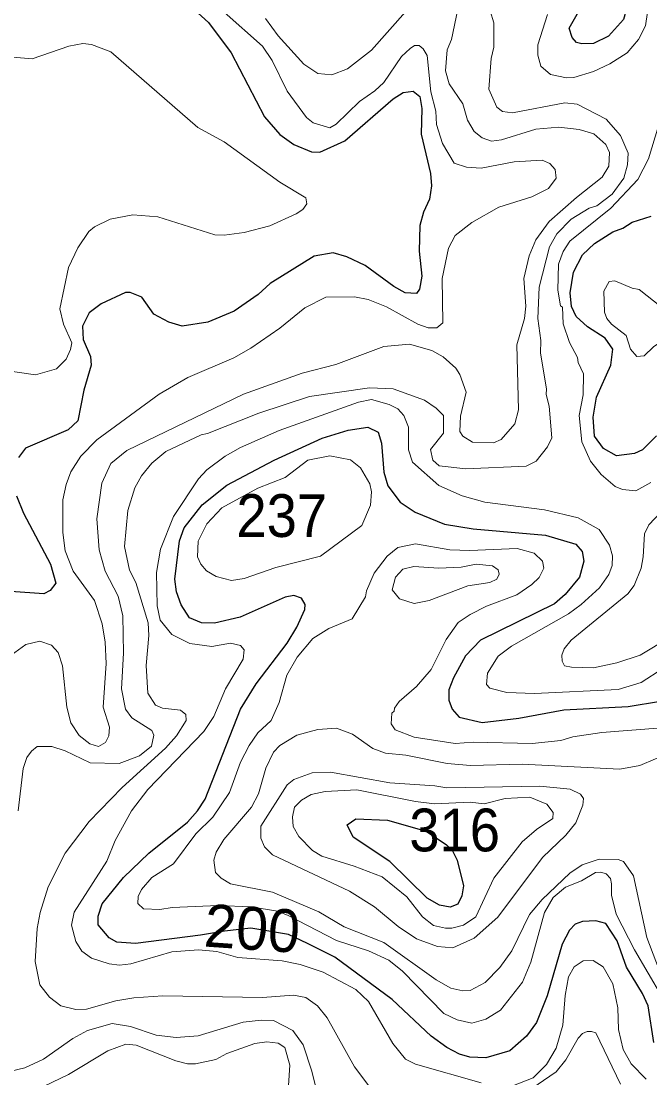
# Model space of a CAD drawing. Extents: x 673.6 to 698.9, y 7012 to 7040.1.
# Drawn here: x 676.978 to 678.153, y 7028.029 to 7030.005 of the extents above; entities that cross this region are included whole.
import ezdxf
from ezdxf.enums import TextEntityAlignment as Align

# ---------------------------------------------------------------- set-up
doc = ezdxf.new("R2010")
doc.units = 0
doc.header["$LTSCALE"] = 0.032
doc.layers.add('1', color=7, linetype='Continuous', lineweight=25)
doc.layers.add('2', color=7, linetype='Continuous', lineweight=13)
doc.layers.add('21', color=7, linetype='Continuous')
doc.layers.add('61', color=7, linetype='Continuous')

msp = doc.modelspace()

# ---------------------------------------------------------------- linework, layer by layer
at = {"layer": '1'}
for points in [[(678.0411, 7030.152), (678.055, 7030.1506), (678.0674, 7030.144), (678.0753, 7030.1312), (678.1044, 7030.0835), (678.1131, 7030.0614), (678.1126, 7030.0395), (678.1039, 7030.0088), (678.0755, 7029.9773), (678.0473, 7029.9638), (678.0256, 7029.9627), (678.016, 7029.9657), (678.0077, 7029.9748), (678.002, 7029.9921), (678.0193, 7030.0227), (678.0451, 7030.0581), (678.0459, 7030.0806), (678.024, 7030.1306), (678.0252, 7030.1378), (678.0316, 7030.1469)], [(677.7731, 7028.4653), (677.7832, 7028.4554), (677.7926, 7028.4367), (677.8046, 7028.3884), (677.8016, 7028.3696), (677.7941, 7028.3539), (677.7799, 7028.3486), (677.7597, 7028.3521), (677.7368, 7028.3655), (677.6671, 7028.4341), (677.5986, 7028.4792), (677.5871, 7028.5023), (677.6031, 7028.514), (677.6623, 7028.5114), (677.7346, 7028.4909)]]:
    msp.add_lwpolyline(points, close=True, dxfattribs=at)
for points in [[(677.2764, 7030.0503), (677.3282, 7030.0026), (677.3702, 7029.9463), (677.4325, 7029.8263), (677.4613, 7029.7932), (677.4875, 7029.7745), (677.5207, 7029.7609), (677.5362, 7029.7607), (677.5826, 7029.7816), (677.6731, 7029.8602), (677.6916, 7029.872), (677.7104, 7029.8746), (677.723, 7029.8648), (677.7264, 7029.8423), (677.7256, 7029.7942), (677.7428, 7029.7203), (677.7445, 7029.6977), (677.7412, 7029.6727), (677.7299, 7029.6483), (677.7232, 7029.6233), (677.7215, 7029.5752), (677.7264, 7029.5284), (677.7225, 7029.5043), (677.7165, 7029.4961), (677.6956, 7029.4976), (677.6743, 7029.5093), (677.6208, 7029.5483), (677.5867, 7029.5649), (677.5612, 7029.5722), (677.5253, 7029.5661), (677.443, 7029.5146), (677.4208, 7029.4945), (677.3756, 7029.4628), (677.3266, 7029.4424), (677.2787, 7029.4352), (677.2535, 7029.4424), (677.2257, 7029.4577), (677.2031, 7029.489), (677.1814, 7029.4978), (677.1725, 7029.4983), (677.1274, 7029.4765), (677.1051, 7029.4601), (677.0921, 7029.435), (677.0939, 7029.4098), (677.1073, 7029.3783), (677.1084, 7029.3624), (677.0947, 7029.3152), (677.0839, 7029.258), (677.0656, 7029.2411), (676.9858, 7029.2072), (676.9729, 7029.1894)], [(678.1651, 7029.2297), (678.1392, 7029.2036), (678.1245, 7029.197), (678.0908, 7029.1928), (678.0663, 7029.2064), (678.0493, 7029.2292), (678.0471, 7029.265), (678.0534, 7029.3025), (678.0797, 7029.3621), (678.0838, 7029.3922), (678.0696, 7029.4123), (678.0362, 7029.4338), (678.0149, 7029.4532), (678.0067, 7029.4721), (678.0042, 7029.4975), (678.0104, 7029.5362), (678.0272, 7029.5682), (678.0492, 7029.5896), (678.0835, 7029.6116), (678.1024, 7029.6182), (678.12, 7029.6293), (678.1554, 7029.6405)], [(678.1606, 7028.0954), (678.1497, 7028.164), (678.1395, 7028.1873), (678.1092, 7028.2366), (678.0919, 7028.2859), (678.0706, 7028.3178), (678.0522, 7028.3232), (678.0273, 7028.3216), (678.0136, 7028.3168), (678.0028, 7028.3055), (677.989, 7028.2796), (677.9609, 7028.1828), (677.9411, 7028.133), (677.9221, 7028.1073), (677.8914, 7028.0797), (677.8464, 7028.067), (677.8167, 7028.0682), (677.7968, 7028.0736), (677.7732, 7028.0859), (677.7443, 7028.1074), (677.671, 7028.1756), (677.5641, 7028.2549), (677.5131, 7028.2804), (677.4772, 7028.2974), (677.4069, 7028.3091), (677.3581, 7028.3034), (677.3127, 7028.2963), (677.1916, 7028.2806), (677.1565, 7028.2831), (677.1424, 7028.2911), (677.1217, 7028.3154), (677.1217, 7028.3315), (677.1293, 7028.3549), (677.1689, 7028.4042), (677.2166, 7028.4495), (677.2885, 7028.5076), (677.3076, 7028.5286), (677.3215, 7028.5505), (677.3875, 7028.7186), (677.4172, 7028.7663), (677.4747, 7028.8423), (677.493, 7028.8722), (677.5078, 7028.9052), (677.5084, 7028.9147), (677.5016, 7028.9261), (677.4874, 7028.9313), (677.4713, 7028.928), (677.3871, 7028.8907), (677.3389, 7028.8797), (677.3149, 7028.8804), (677.2924, 7028.8898), (677.2768, 7028.9137), (677.2684, 7028.9381), (677.2647, 7028.962), (677.2738, 7029.0337), (677.2827, 7029.0579), (677.3159, 7029.1009), (677.3624, 7029.1379), (677.4507, 7029.1847), (677.5404, 7029.2254), (677.5888, 7029.2404), (677.6257, 7029.246), (677.6453, 7029.237), (677.6516, 7029.2165), (677.6557, 7029.1619), (677.6634, 7029.1365), (677.6865, 7029.1062), (677.7145, 7029.0874), (677.7693, 7029.065), (677.8224, 7029.0563), (677.9577, 7029.0441), (678.0143, 7029.0272), (678.0262, 7029.0139), (678.0296, 7028.9958), (678.0214, 7028.9655), (677.9946, 7028.9334), (677.9748, 7028.916), (677.8365, 7028.848), (677.8084, 7028.8184), (677.7858, 7028.7773), (677.7774, 7028.7551), (677.7774, 7028.7358)], [(676.969, 7029.1177), (676.9821, 7029.0856), (677.0324, 7028.9898), (677.0423, 7028.9547), (677.032, 7028.9405), (677.0202, 7028.9347), (676.9585, 7028.9388)], [(677.7774, 7028.7358), (677.7832, 7028.7186), (677.7965, 7028.7036), (677.8393, 7028.694), (677.9079, 7028.702), (677.9922, 7028.7173)], [(677.9922, 7028.7173), (678.1126, 7028.7235), (678.1726, 7028.7339)]]:
    msp.add_lwpolyline(points, dxfattribs=at)
at = {"layer": '2'}
for points in [[(677.1651, 7028.7567), (677.1693, 7028.8235), (677.1676, 7028.8936), (677.1593, 7028.93), (677.1349, 7028.9771), (677.1237, 7029.0167), (677.1192, 7029.0749), (677.1287, 7029.1417), (677.1451, 7029.1785), (677.1753, 7029.2027), (677.3933, 7029.3081), (677.5029, 7029.3472), (677.5659, 7029.3632), (677.6554, 7029.3972), (677.7034, 7029.4014), (677.7455, 7029.3894), (677.7665, 7029.378), (677.7903, 7029.3565), (677.7976, 7029.3445), (677.8093, 7029.3114), (677.7988, 7029.2667), (677.798, 7029.2382), (677.8032, 7029.2293), (677.8214, 7029.2183), (677.8609, 7029.2166), (677.8748, 7029.2231), (677.9003, 7029.2523), (677.9072, 7029.2783), (677.904, 7029.4001), (677.9187, 7029.4492), (677.9212, 7029.4724), (677.9171, 7029.5241), (677.9272, 7029.5665), (677.9398, 7029.5965), (677.965, 7029.631), (678.0156, 7029.6759), (678.0641, 7029.7138), (678.0765, 7029.7341), (678.0772, 7029.7596), (678.0706, 7029.7745), (678.048, 7029.7947), (678.0206, 7029.8028), (677.9828, 7029.8073), (677.9399, 7029.8032), (677.8757, 7029.7835), (677.857, 7029.7812), (677.8392, 7029.7871), (677.8248, 7029.7988), (677.812, 7029.8201), (677.8032, 7029.8508), (677.7781, 7029.8883), (677.7709, 7029.9123), (677.7741, 7029.9517), (677.7824, 7029.9708), (677.803, 7030.0704)], [(677.3569, 7030.0224), (677.4287, 7029.9588), (677.4472, 7029.932), (677.475, 7029.8747), (677.5108, 7029.8252), (677.5233, 7029.8152), (677.5548, 7029.8059), (677.5663, 7029.813), (677.6101, 7029.8549), (677.6386, 7029.8754), (677.6555, 7029.891), (677.6889, 7029.9391), (677.7052, 7029.954), (677.7132, 7029.9596), (677.722, 7029.9596), (677.7293, 7029.9537), (677.7364, 7029.9414), (677.7437, 7029.8731), (677.7527, 7029.837), (677.7544, 7029.8124), (677.7655, 7029.7768), (677.7874, 7029.7401), (677.8103, 7029.7323), (677.8377, 7029.7302), (677.899, 7029.7424), (677.9516, 7029.7457), (677.9657, 7029.739), (677.9762, 7029.7282), (677.9778, 7029.7119), (677.9636, 7029.6927), (677.9321, 7029.6769), (677.8704, 7029.6575), (677.8204, 7029.6292), (677.789, 7029.6044), (677.7768, 7029.5809), (677.765, 7029.5244), (677.7658, 7029.4413), (677.7546, 7029.4321), (677.7383, 7029.4318), (677.7195, 7029.4386), (677.6604, 7029.4714), (677.6261, 7029.4849), (677.6006, 7029.4902), (677.5473, 7029.4893), (677.508, 7029.4695), (677.4615, 7029.4315), (677.4073, 7029.3939), (677.3755, 7029.376), (677.2895, 7029.3392)], [(677.6964, 7030.0229), (677.6327, 7029.9511), (677.5877, 7029.9163), (677.5585, 7029.9051), (677.5322, 7029.9078), (677.5059, 7029.925), (677.4582, 7029.9777), (677.4343, 7030.0101)], [(677.8545, 7030.0246), (677.861, 7030.0021), (677.8612, 7029.957), (677.8563, 7029.9356), (677.8522, 7029.8781), (677.8666, 7029.8444), (677.8772, 7029.8362), (677.8961, 7029.8338), (677.9943, 7029.8525), (678.017, 7029.8502), (678.0715, 7029.8221), (678.0983, 7029.7915), (678.1125, 7029.7585), (678.1112, 7029.737), (678.1043, 7029.7118), (678.0825, 7029.6819)], [(678.1488, 7030.0224), (678.1446, 7029.9964), (678.1319, 7029.9711), (678.1103, 7029.9464), (678.0781, 7029.9258), (678.0479, 7029.9114), (678.011, 7029.9003), (677.9971, 7029.8995), (677.9675, 7029.9056), (677.9489, 7029.9214), (677.9434, 7029.9417), (677.9437, 7029.9614), (677.9614, 7030.0178)], [(676.9404, 7029.3535), (677.0045, 7029.344), (677.044, 7029.355), (677.0618, 7029.3734), (677.07, 7029.3913), (677.0722, 7029.404), (677.0571, 7029.4387), (677.0502, 7029.4675), (677.0661, 7029.5449), (677.0836, 7029.5816), (677.1043, 7029.6118), (677.1148, 7029.6211), (677.1442, 7029.6354), (677.1866, 7029.643), (677.2331, 7029.6397), (677.3399, 7029.6061), (677.3569, 7029.6053), (677.3948, 7029.6103), (677.4424, 7029.6226), (677.4917, 7029.6448), (677.5043, 7029.6535), (677.5119, 7029.6639), (677.5101, 7029.6751), (677.4613, 7029.7042), (677.3573, 7029.7798), (677.3082, 7029.8064), (677.1454, 7029.9479), (677.1095, 7029.962), (677.093, 7029.9635), (677.0671, 7029.9585), (676.998, 7029.9348), (676.9478, 7029.9396)], [(678.1548, 7029.1428), (678.1268, 7029.1274), (678.1015, 7029.1294), (678.0882, 7029.1351), (678.0617, 7029.1576), (678.0422, 7029.1824), (678.0256, 7029.219), (678.0207, 7029.2681), (678.0281, 7029.3069), (678.0287, 7029.3461), (678.019, 7029.3671), (678.018, 7029.3767), (678.0029, 7029.4043), (677.991, 7029.4393), (677.9894, 7029.4706), (677.9862, 7029.4733), (677.9812, 7029.5025), (677.982, 7029.551), (677.9912, 7029.5744), (678.0031, 7029.5942), (678.0801, 7029.6556), (678.1305, 7029.7093), (678.1503, 7029.7479), (678.1688, 7029.8097)], [(678.0825, 7029.6819), (678.0541, 7029.6599), (678.0398, 7029.6558), (678.0056, 7029.6354), (677.9789, 7029.608), (677.9655, 7029.5835)], [(677.9655, 7029.5835), (677.9458, 7029.5079), (677.9434, 7029.4494), (677.9491, 7029.408), (677.9484, 7029.3847), (677.9597, 7029.318), (677.9591, 7029.307), (677.9648, 7029.2857), (677.9697, 7029.2264), (677.9618, 7029.2096), (677.9402, 7029.1823), (677.9215, 7029.1732), (677.8089, 7029.1681), (677.7589, 7029.1741), (677.7471, 7029.1844), (677.7429, 7029.2047), (677.7675, 7029.235), (677.7672, 7029.2678), (677.7537, 7029.282), (677.7316, 7029.2967), (677.6731, 7029.3177), (677.6287, 7029.32), (677.5167, 7029.3038), (677.4221, 7029.2723), (677.3261, 7029.2341), (677.3139, 7029.2321), (677.2479, 7029.2007), (677.2219, 7029.1788), (677.2024, 7029.1552), (677.1904, 7029.1328), (677.1773, 7029.0901), (677.171, 7029.0231), (677.1801, 7028.9787), (677.1923, 7028.956), (677.2153, 7028.8804), (677.2161, 7028.8567), (677.2112, 7028.8003), (677.2142, 7028.7485), (677.2287, 7028.7264), (677.2418, 7028.7204), (677.2753, 7028.7167), (677.2856, 7028.7086), (677.2859, 7028.6974), (677.2681, 7028.6687), (677.2476, 7028.6457), (677.1663, 7028.5726), (677.1049, 7028.5089), (677.0599, 7028.4495), (677.0282, 7028.3868), (677.0133, 7028.3387), (677.0074, 7028.3085), (677.0041, 7028.2472), (677.0126, 7028.2031), (677.0307, 7028.18), (677.052, 7028.1639), (677.0802, 7028.1574), (677.0999, 7028.1581), (677.1546, 7028.1737), (677.1883, 7028.1793), (677.2425, 7028.1827), (677.4288, 7028.1794), (677.4869, 7028.1837), (677.5099, 7028.1798), (677.5314, 7028.1641), (677.5497, 7028.1414), (677.6006, 7028.0499), (677.6294, 7028.0119)], [(677.2895, 7029.3392), (677.2354, 7029.3078), (677.1194, 7029.2225), (677.0892, 7029.1917), (677.0705, 7029.1628), (677.0617, 7029.1388)], [(677.715, 7028.0551), (677.6961, 7028.0645), (677.6726, 7028.0934), (677.627, 7028.1721), (677.6033, 7028.1946), (677.5423, 7028.2271), (677.4993, 7028.2412), (677.4658, 7028.2484), (677.3825, 7028.2543), (677.3435, 7028.2657), (677.3094, 7028.269), (677.2592, 7028.2648), (677.1825, 7028.2424), (677.1616, 7028.2404), (677.1425, 7028.2426), (677.1091, 7028.2531), (677.0912, 7028.2665), (677.0798, 7028.2844), (677.0715, 7028.3148), (677.0771, 7028.3394), (677.1377, 7028.4344), (677.1533, 7028.473), (677.1839, 7028.5284), (677.2144, 7028.5685), (677.3192, 7028.6768), (677.3379, 7028.7051), (677.3598, 7028.7569), (677.393, 7028.8121), (677.3943, 7028.8297), (677.3875, 7028.8379), (677.3689, 7028.8425), (677.3342, 7028.8361), (677.2928, 7028.8418), (677.2594, 7028.8585), (677.2375, 7028.8854), (677.2318, 7028.9122), (677.231, 7028.9744), (677.2381, 7029.0178), (677.2622, 7029.0793), (677.3094, 7029.1497), (677.3247, 7029.1665), (677.3588, 7029.1917), (677.3875, 7029.2082), (677.4597, 7029.2397), (677.6081, 7029.2929), (677.6327, 7029.2979), (677.6656, 7029.2888), (677.682, 7029.2805), (677.6933, 7029.2678), (677.7016, 7029.246), (677.7016, 7029.2037), (677.7092, 7029.1806), (677.7583, 7029.1373), (677.8018, 7029.1179), (677.8444, 7029.1057), (677.9559, 7029.0917), (678.019, 7029.0768), (678.058, 7029.0548), (678.0774, 7029.0258), (678.083, 7029.0053), (678.0822, 7028.9874), (678.0765, 7028.9709), (678.059, 7028.946), (678.0246, 7028.9146), (678.0006, 7028.8972), (677.8943, 7028.8368), (677.8693, 7028.8178), (677.8495, 7028.7861), (677.8474, 7028.7647), (677.854, 7028.7581), (677.8859, 7028.7498), (677.9376, 7028.7481), (678.0936, 7028.7553), (678.137, 7028.7686), (678.1772, 7028.7948)], [(677.0617, 7029.1388), (677.0559, 7029.1105), (677.0557, 7029.0493), (677.06, 7029.0149), (677.0752, 7028.9769), (677.1146, 7028.9222), (677.1291, 7028.8785), (677.1347, 7028.8443), (677.1365, 7028.8044), (677.1307, 7028.7226), (677.1428, 7028.6852), (677.1414, 7028.6691), (677.1355, 7028.6562), (677.1221, 7028.6488), (677.1058, 7028.6542), (677.0862, 7028.6696), (677.0707, 7028.6935), (677.0632, 7028.7228), (677.055, 7028.7999), (677.0468, 7028.8245), (677.0344, 7028.8384), (677.0129, 7028.8458), (676.9865, 7028.84), (676.9588, 7028.8196)], [(678.1896, 7028.8531), (678.1349, 7028.8201), (678.0915, 7028.8053), (678.0473, 7028.7959), (678.0062, 7028.7974), (677.9936, 7028.8001), (677.9891, 7028.8084), (677.9883, 7028.8196), (677.9929, 7028.8319), (678.006, 7028.8477), (678.1118, 7028.9348), (678.1236, 7028.9498), (678.1365, 7028.9827), (678.1406, 7029.0037), (678.1428, 7029.0469), (678.1511, 7029.0634), (678.1854, 7029.0997)], [(677.7677, 7028.1496), (677.6905, 7028.2286), (677.6653, 7028.2495), (677.6271, 7028.2668), (677.5669, 7028.2863), (677.4768, 7028.3329), (677.4567, 7028.3411), (677.4079, 7028.3494), (677.346, 7028.3517), (677.2599, 7028.3481), (677.237, 7028.3439), (677.2066, 7028.3453), (677.1957, 7028.3555), (677.1963, 7028.3685), (677.2026, 7028.3814), (677.2219, 7028.4038), (677.2622, 7028.4294), (677.304, 7028.486), (677.3357, 7028.5171), (677.3671, 7028.5629), (677.388, 7028.6194), (677.4039, 7028.651), (677.42, 7028.6743), (677.4453, 7028.6974), (677.4599, 7028.7312), (677.4743, 7028.7821), (677.4938, 7028.8163), (677.5232, 7028.8507), (677.5526, 7028.8699), (677.5962, 7028.8877), (677.6217, 7028.929), (677.6231, 7028.9399), (677.6378, 7028.9729), (677.6618, 7029.0048), (677.6821, 7029.0209), (677.715, 7029.0283), (677.7793, 7029.0169), (677.8164, 7029.0153), (677.9047, 7029.0192), (677.9368, 7029.0103), (677.9525, 7028.9956), (677.9547, 7028.9825), (677.9459, 7028.9652), (677.9325, 7028.9519), (677.9042, 7028.9324), (677.8477, 7028.9115), (677.8168, 7028.896), (677.7949, 7028.8807), (677.7723, 7028.8489), (677.7443, 7028.7931), (677.7168, 7028.7615), (677.6846, 7028.7333), (677.6757, 7028.7209), (677.6751, 7028.7151), (677.6706, 7028.7113), (677.6691, 7028.6915), (677.677, 7028.6803), (677.7121, 7028.6663), (677.7892, 7028.6545), (677.8227, 7028.6568), (677.933, 7028.6545), (677.9865, 7028.6603), (678.0092, 7028.6668), (678.063, 7028.675), (678.1755, 7028.6838)], [(677.2216, 7028.6498), (677.2258, 7028.67), (677.222, 7028.6788), (677.1846, 7028.7025), (677.1728, 7028.7191), (677.1651, 7028.7567)], [(678.1929, 7028.6382), (678.1344, 7028.6135), (678.0966, 7028.6068), (677.9142, 7028.6158), (677.8176, 7028.6134), (677.7742, 7028.6175), (677.6968, 7028.633), (677.6587, 7028.6364), (677.6353, 7028.645), (677.5972, 7028.672), (677.567, 7028.6832), (677.532, 7028.681), (677.4928, 7028.6699), (677.4611, 7028.6506), (677.4492, 7028.6386), (677.4353, 7028.6085), (677.4215, 7028.5603), (677.4086, 7028.5357), (677.3564, 7028.475), (677.3424, 7028.4511), (677.3378, 7028.4364), (677.3413, 7028.4135), (677.3515, 7028.4026), (677.3691, 7028.3919), (677.4474, 7028.3766), (677.5341, 7028.3397), (677.5815, 7028.312), (677.6554, 7028.2824), (677.7532, 7028.2124), (677.7806, 7028.1968), (677.8034, 7028.1919), (677.817, 7028.1928), (677.8449, 7028.2078), (677.8725, 7028.236), (677.8949, 7028.2666), (677.9277, 7028.3348), (677.9514, 7028.3629), (678.0031, 7028.4124), (678.0265, 7028.428), (678.0584, 7028.4383), (678.0938, 7028.4376), (678.1038, 7028.434), (678.1225, 7028.4074), (678.1472, 7028.2921), (678.176, 7028.2165)], [(676.972, 7028.5288), (676.9817, 7028.6081), (676.9884, 7028.6287), (676.9968, 7028.6405), (677.0077, 7028.6487), (677.0352, 7028.6487), (677.0598, 7028.641), (677.1068, 7028.6184), (677.1607, 7028.6175), (677.1991, 7028.6316), (677.2216, 7028.6498)], [(678.0252, 7028.398), (677.995, 7028.386), (677.9723, 7028.3669), (677.956, 7028.3387), (677.9302, 7028.246), (677.9147, 7028.2086)], [(678.1753, 7028.1815), (678.1243, 7028.2689), (678.0902, 7028.3352), (678.0813, 7028.3711), (678.0813, 7028.3923), (678.0791, 7028.4019), (678.0714, 7028.4111), (678.0611, 7028.4139), (678.0516, 7028.4135), (678.0252, 7028.398)], [(678.1458, 7028.0271), (678.1178, 7028.0556), (678.1033, 7028.0823), (678.0946, 7028.1196), (678.0929, 7028.1606), (678.0839, 7028.2049), (678.0659, 7028.2367), (678.0468, 7028.2487), (678.028, 7028.2485), (678.0115, 7028.2369), (678.001, 7028.2181), (677.9946, 7028.1835), (677.9902, 7028.1278), (677.9777, 7028.0847), (677.9599, 7028.0544), (677.9348, 7028.0296), (677.898, 7028.0153)], [(677.9147, 7028.2086), (677.8738, 7028.1559), (677.8461, 7028.1391), (677.8202, 7028.1319), (677.7926, 7028.1379), (677.7677, 7028.1496)], [(677.5372, 7027.9765), (677.5211, 7028.0419), (677.505, 7028.0914), (677.4855, 7028.118), (677.4493, 7028.1367), (677.4266, 7028.1375), (677.3925, 7028.1334), (677.3087, 7028.108), (677.2674, 7028.1048), (677.2302, 7028.1089), (677.1818, 7028.1254), (677.1481, 7028.1309), (677.1019, 7028.1178), (677.0743, 7028.1032), (677.0194, 7028.0643), (676.9846, 7028.0478), (676.9561, 7028.0413)], [(677.9203, 7028.0012), (677.9778, 7028.0407), (677.9961, 7028.0632), (678.0188, 7028.1037), (678.0273, 7028.1124), (678.0359, 7028.116), (678.0438, 7028.1162), (678.052, 7028.1134), (678.098, 7028.0173)], [(677.0207, 7028.0141), (677.066, 7028.0359), (677.14, 7028.0802), (677.1735, 7028.0922), (677.1926, 7028.0906), (677.2666, 7028.0611), (677.2889, 7028.0555), (677.3035, 7028.0554), (677.3415, 7028.064), (677.3624, 7028.0751), (677.4148, 7028.0934), (677.4368, 7028.0966), (677.4581, 7028.094), (677.4709, 7028.0861), (677.4799, 7028.0528), (677.4773, 7028.0153)], [(677.8376, 7028.0198), (677.715, 7028.0551)]]:
    msp.add_lwpolyline(points, dxfattribs=at)
for points in [[(678.1331, 7029.5039), (678.1201, 7029.506), (678.0875, 7029.5195), (678.0769, 7029.5184), (678.0667, 7029.5005), (678.0682, 7029.461), (678.0725, 7029.4492), (678.0813, 7029.4385), (678.1084, 7029.4178), (678.1166, 7029.3921), (678.1284, 7029.3786), (678.1425, 7029.3795), (678.1598, 7029.3967), (678.1932, 7029.4194), (678.1944, 7029.4417), (678.175, 7029.4704)], [(677.3947, 7028.9632), (677.4535, 7028.984), (677.5375, 7029.005), (677.6143, 7029.062), (677.631, 7029.1004), (677.6328, 7029.1251), (677.6293, 7029.14), (677.6122, 7029.1703), (677.5931, 7029.1853), (677.5545, 7029.1926), (677.5135, 7029.1847), (677.4714, 7029.1523), (677.4201, 7029.1324), (677.3531, 7029.0955), (677.3248, 7029.0656), (677.3089, 7029.033), (677.3074, 7029.0038), (677.3138, 7028.99), (677.3242, 7028.9778), (677.3425, 7028.9672), (677.3711, 7028.9594)], [(677.7118, 7028.9859), (677.7587, 7028.9824), (677.8, 7028.9844), (677.8283, 7028.9897), (677.8588, 7028.9866), (677.8692, 7028.9796), (677.8713, 7028.9711), (677.8669, 7028.9621), (677.8536, 7028.9555), (677.8128, 7028.9494), (677.7403, 7028.9218), (677.7122, 7028.9167), (677.685, 7028.9249), (677.6715, 7028.9421), (677.6772, 7028.9659), (677.691, 7028.9806)], [(677.9522, 7028.4415), (677.9957, 7028.4833), (678.0143, 7028.5064), (678.0277, 7028.5392), (678.0287, 7028.5519), (678.0235, 7028.56), (678.0042, 7028.569), (677.9474, 7028.5747), (677.7734, 7028.5715), (677.7511, 7028.5755), (677.6667, 7028.581), (677.5559, 7028.601), (677.5218, 7028.5995), (677.4872, 7028.5874), (677.4752, 7028.5772), (677.4257, 7028.4999), (677.4257, 7028.4773), (677.4324, 7028.4612), (677.4476, 7028.4463), (677.5913, 7028.3785), (677.638, 7028.3494), (677.6826, 7028.3127), (677.7167, 7028.2893), (677.7557, 7028.2749), (677.7845, 7028.2725), (677.8244, 7028.2904), (677.8688, 7028.3301)], [(677.8615, 7028.4027), (677.9142, 7028.4709), (677.9411, 7028.4938), (677.9714, 7028.5142), (677.9722, 7028.5256), (677.9604, 7028.5411), (677.9286, 7028.5542), (677.8826, 7028.5517), (677.8435, 7028.542), (677.8168, 7028.5451), (677.7504, 7028.5419), (677.7146, 7028.546), (677.6049, 7028.5682), (677.5463, 7028.565), (677.52, 7028.5592), (677.5017, 7028.5487), (677.4889, 7028.5357), (677.4849, 7028.5176), (677.4861, 7028.4996), (677.4968, 7028.4806), (677.5221, 7028.4544), (677.5395, 7028.4439), (677.6002, 7028.4251), (677.6523, 7028.405), (677.6984, 7028.3677), (677.7278, 7028.3302), (677.7485, 7028.3142), (677.7707, 7028.309), (677.783, 7028.3094), (677.8046, 7028.3149), (677.8277, 7028.3303)]]:
    msp.add_lwpolyline(points, close=True, dxfattribs=at)

# ---------------------------------------------------------------- texts
at = {"layer": '21', "width": 0.95}
for s, p in [('237', (677.3801, 7029.0408)), ('316', (677.7033, 7028.4529))]:
    msp.add_text(s, height=0.08, dxfattribs=at).set_placement(p)
at = {"layer": '61'}
msp.add_text('200', height=0.08, rotation=356.07, dxfattribs=at).set_placement((677.4069, 7028.269), align=Align.CENTER)

doc.saveas('drawing.dxf')
